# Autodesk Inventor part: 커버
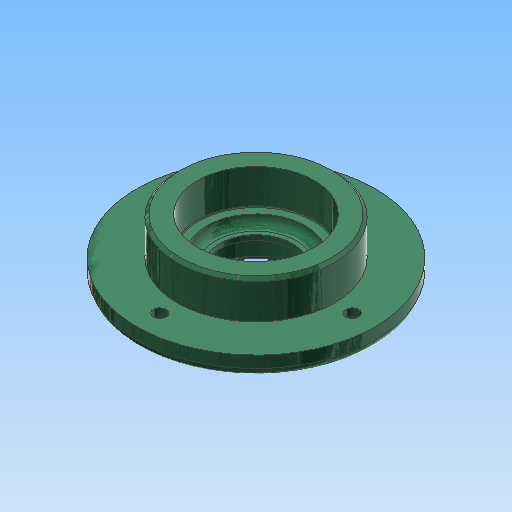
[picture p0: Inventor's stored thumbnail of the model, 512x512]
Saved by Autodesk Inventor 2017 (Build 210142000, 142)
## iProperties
Company: 한국ATC센터
Created: 2014-10
Part Number: 커버
Document SubType Name: Modeling
Designer: KYOUNG IL JANG
Density: 2.71 g/cm^3
Mass: 121.214 g
Surface Area: 161.165 cm^2
Volume: 44.7286 cm^3
Material: 알루미늄 6061
Appearance: 알루미늄 - 평지
Author: KYOUNG IL JANG
Revision Number: 1
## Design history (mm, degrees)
sketch "스케치1"
  geometry: C1 r 41 at (0, 0); 1 further point
  constraints: 1 centre point, 1 coincident
  dimensions: "d0" = 82 diameter of C1
extrude "돌출1" new body sketch "스케치1" distance "d1" = 7; taper "d2" = 0 deg
sketch "스케치2"
  geometry: C1 r 27 at (0, 0); 1 further point
  constraints: 1 centre point, 1 coincident
  dimensions: "d3" = 54 diameter of C1
extrude "돌출2" join sketch "스케치2" distance "d4" = 13; taper "d5" = 0 deg
sketch "스케치3"
  geometry: C1 r 20 at (0, 0); 1 further point
  constraints: 1 centre point, 1 coincident
  dimensions: "d6" = 40 diameter of C1
extrude "돌출3" join sketch "스케치3" distance "d7" = 5; taper "d8" = 0 deg
hole "구멍1" diameter "d11" = 25; stored, may be unused: countersink angle "d15" = 90 deg, drill point angle "d17" = 118 deg; dims "d9" = 10, "d10" = 10, "d12" = 6, "d13" = 32, "d14" = 8.3, "d16" = 8
hole "구멍2" diameter "d20" = 34; stored, may be unused: countersink angle "d24" = 90 deg, drill point angle "d26" = 0 deg; dims "d18" = 10, "d19" = 10, "d21" = 6, "d22" = 40, "d23" = 12, "d25" = 3
fillet "모깎기2" dims "d34" = 3
fillet "모깎기1" dims "d27" = 0.3
chamfer "모따기1" distance "d28" = 1; stored, may be unused: second distance "d29" = 2, angle "d30" = 45 deg
chamfer "모따기2" distance "d31" = 1.2; stored, may be unused: second distance "d32" = 2, angle "d33" = 30 deg
sketch "스케치4" dims "d35" = 66
  geometry: 3 further points
  constraints: 2 horizontal alignment, 1 coincident, 2 other
hole "구멍3" sketch "스케치4" at (33, 0) diameter "d36" = 4.5; stored, may be unused: countersink angle "d40" = 90 deg, drill point angle "d42" = 118 deg; dims "d37" = 6, "d38" = 8, "d39" = 4.4, "d41" = 13
node "솔리드1"
pattern_circular "원형 패턴1" dims angle "d44" = 360 deg
